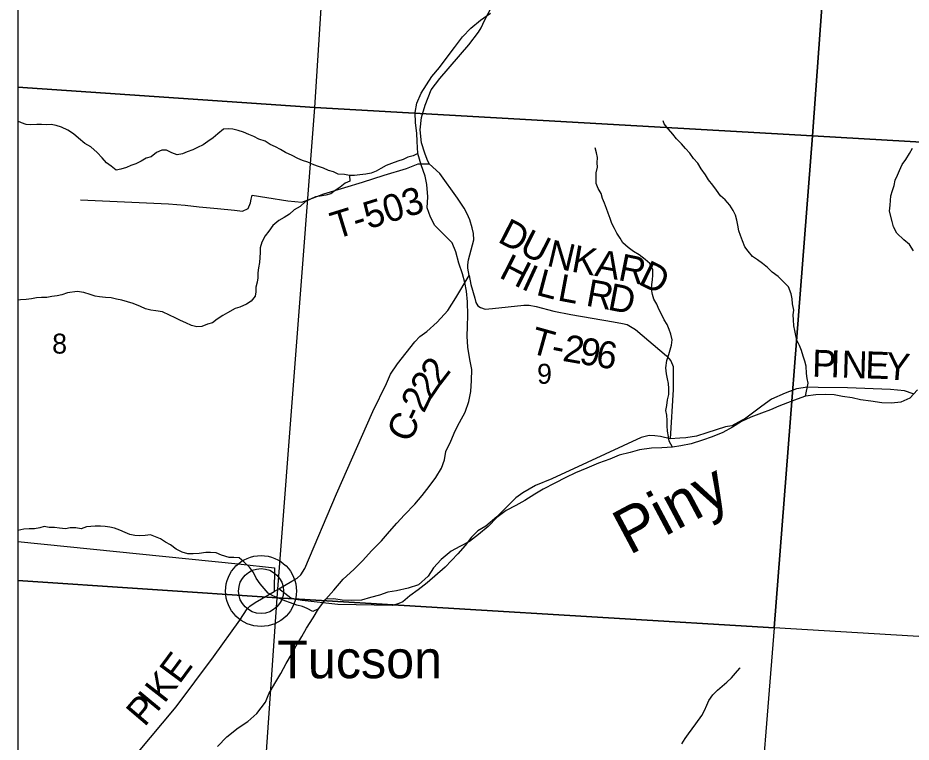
# Model space of a CAD drawing. Extents: x -13.1 to 43.1, y 0 to 22.
# Drawn here: x 2.1 to 3.976, y 14.849 to 16.37 of the extents above; entities that cross this region are included whole.
import ezdxf

# ---------------------------------------------------------------- set-up
doc = ezdxf.new("R2010")
doc.units = 0
for name, color, linetype in [('GM_X_Corporation', 7, 'Continuous'), ('GM_X_County_Road', 7, 'Continuous'), ('GM_X_County_Road_Text', 7, 'Continuous'), ('GM_X_Minor_River', 7, 'Continuous'), ('GM_X_Minor_River_Text', 7, 'Continuous'), ('GM_X_Section_Text', 7, 'Continuous'), ('GM_X_Township_Road', 7, 'Continuous'), ('GM_X_Township_Road_Text', 7, 'Continuous'), ('GM_X_Unincorporated', 7, 'Continuous'), ('GM_X_Unincorporated_Location', 7, 'Continuous'), ('GM_X_Unincorporated_Text', 7, 'Continuous'), ('SH_Data', 7, 'Continuous')]:
    doc.layers.add(name, color=color, linetype=linetype)

msp = doc.modelspace()

# ---------------------------------------------------------------- linework, layer by layer
at = {"layer": 'GM_X_Corporation'}
for points in [[(7.0807, 20.9), (2.1, 20.9), (2.1, 14.1), (6.6193, 14.1), (6.6994, 15.2069), (6.7531, 15.956), (6.8236, 16.9075), (6.9509, 19.0179), (7.0108, 19.8446), (7.0164, 19.8954), (7.0617, 20.6133)], [(7.0804, 20.9), (2.1, 20.9), (2.1, 14.1), (6.619, 14.1), (6.6992, 15.2074), (6.7528, 15.9566), (6.8234, 16.908), (6.8365, 17.1257), (6.9507, 19.0184), (6.9616, 19.1692), (7.0106, 19.8452), (7.0162, 19.896), (7.0615, 20.6138)], [(2.1, 17.2165), (2.1, 16.2245), (2.7236, 16.1815), (2.7867, 17.1698)], [(2.1, 17.2152), (2.1, 14.1), (6.619, 14.1), (6.6992, 15.2074), (6.7528, 15.9566), (6.8234, 16.908), (4.4304, 17.0575), (3.8328, 17.0966), (2.8442, 17.1637), (2.1437, 17.2135)], [(2.8499, 17.1651), (3.8395, 17.0976), (3.7693, 16.1222), (2.7236, 16.1815), (2.7867, 17.1698)], [(3.8395, 17.0976), (4.8272, 17.0344), (4.7589, 16.0643), (3.7693, 16.1222)], [(2.1, 16.2245), (2.1, 15.1883), (2.6447, 15.1518), (2.7236, 16.1815)], [(2.7236, 16.1815), (3.7693, 16.1222), (3.6885, 15.0891), (2.6447, 15.1518)], [(3.7693, 16.1222), (4.7589, 16.0643), (4.6921, 15.0289), (3.6885, 15.0891)], [(2.1, 15.1883), (2.1, 14.2382), (2.5786, 14.2031), (2.6447, 15.1518)], [(2.6447, 15.1518), (3.6885, 15.0891), (3.6113, 14.1287), (2.5786, 14.2031)], [(4.0665, 14.1), (4.6107, 14.1), (4.6921, 15.0289), (3.6885, 15.0891), (3.6113, 14.1287)]]:
    msp.add_lwpolyline(points, close=True, dxfattribs=at)
at = {"layer": 'GM_X_County_Road'}
for points in [[(3.048, 15.8288), (3.0449, 15.8441), (3.0451, 15.8513), (3.0464, 15.8615), (3.0576, 15.9035), (3.0567, 15.9169), (3.0539, 15.9291), (3.0493, 15.9455), (3.0439, 15.9582), (3.0376, 15.9701), (3.0232, 15.991), (2.9865, 16.0431), (2.964, 16.0633), (2.9597, 16.0725), (2.955, 16.0859), (2.9478, 16.1074), (2.9453, 16.1348), (2.9481, 16.1606), (2.9552, 16.1863), (2.9684, 16.2184), (2.9864, 16.2424), (3.047, 16.3134), (3.0677, 16.3396), (3.0733, 16.3486), (3.0801, 16.364), (3.1423, 16.4836)], [(2.3498, 14.8244), (2.4327, 14.9227), (2.5111, 15.028), (2.5661, 15.1052), (2.5814, 15.1284), (2.5873, 15.1344), (2.5985, 15.1418), (2.6383, 15.1648), (2.6479, 15.1704), (2.6757, 15.1869), (2.6865, 15.1932), (2.6942, 15.2003), (2.7025, 15.2134), (2.7694, 15.3702), (2.8454, 15.5428), (2.8741, 15.6019), (2.8829, 15.6212), (2.8974, 15.6429), (2.9335, 15.6897), (2.9444, 15.7009), (2.9587, 15.7112), (2.9808, 15.7309), (3.0034, 15.7552), (3.02, 15.7815), (3.048, 15.8288)], [(3.9804, 15.5805), (3.9619, 15.5866), (3.9326, 15.5891), (3.8423, 15.5925), (3.7806, 15.5938), (3.7588, 15.5939), (3.7351, 15.5906), (3.7113, 15.5815), (3.6828, 15.5692), (3.6627, 15.5544), (3.629, 15.5292), (3.5997, 15.5131), (3.5863, 15.5107), (3.5468, 15.4986), (3.5253, 15.4915), (3.5031, 15.4877), (3.4905, 15.4872), (3.4699, 15.4858), (3.4494, 15.4908), (3.4376, 15.4921), (3.4258, 15.4924), (3.4093, 15.4882), (3.2958, 15.4361), (3.2215, 15.4015), (3.1873, 15.3878), (3.1606, 15.372), (3.1459, 15.3617), (3.1058, 15.3218), (3.0829, 15.3025), (3.0663, 15.2922), (3.0531, 15.2795), (3.0394, 15.2616), (3.0238, 15.244), (2.9973, 15.216), (2.96, 15.183), (2.941, 15.1689), (2.9232, 15.156), (2.9085, 15.1437), (2.9, 15.1397), (2.887, 15.1354), (2.7719, 15.1378), (2.6973, 15.1462), (2.684, 15.1484), (2.6734, 15.1512), (2.6479, 15.1704)]]:
    msp.add_lwpolyline(points, dxfattribs=at)
at = {"layer": 'GM_X_Minor_River'}
for points in [[(2.6746, 15.0325), (2.6846, 15.0507), (2.6961, 15.0704), (2.7061, 15.0878), (2.7199, 15.1097), (2.7314, 15.1287), (2.7467, 15.1491), (2.7636, 15.168), (2.7835, 15.1907), (2.8056, 15.211), (2.824, 15.2292), (2.8431, 15.2511), (2.8638, 15.2715), (2.8806, 15.2911), (2.8959, 15.3085), (2.912, 15.3259), (2.9334, 15.3486), (2.9495, 15.3667), (2.964, 15.3856), (2.9778, 15.4045), (2.9901, 15.4242), (2.9963, 15.4416), (2.9987, 15.4591), (3.0094, 15.4811), (3.0187, 15.5023), (3.0279, 15.5197), (3.0394, 15.5416), (3.0472, 15.5644), (3.0511, 15.5849), (3.0527, 15.6084), (3.0536, 15.6312), (3.0492, 15.6524), (3.0448, 15.6783), (3.0434, 15.7011), (3.0442, 15.7215), (3.0451, 15.7451), (3.0445, 15.7732), (3.0424, 15.796), (3.0387, 15.8142), (3.0342, 15.8324), (3.026, 15.8545), (3.02, 15.8781), (3.0125, 15.8971), (2.9951, 15.9139), (2.9755, 15.9337), (2.9664, 15.9512), (2.9597, 15.971), (2.9614, 15.9937), (2.9592, 16.0196), (2.9555, 16.0371), (2.9473, 16.0614), (2.9398, 16.085), (2.9384, 16.11), (2.9378, 16.1275), (2.9349, 16.1495), (2.9342, 16.1708), (2.9381, 16.1905), (2.9474, 16.2117), (2.9581, 16.2291), (2.9696, 16.2465), (2.9857, 16.2654), (3.0018, 16.2874), (3.0171, 16.3078), (3.034, 16.3297), (3.0516, 16.3478), (3.0714, 16.3652), (3.0928, 16.3795)], [(3.7545, 15.5753), (3.7602, 15.6026), (3.7581, 15.6125), (3.7567, 15.6228), (3.7554, 15.638), (3.7528, 15.6486), (3.7495, 15.6593), (3.7459, 15.6711), (3.7415, 15.6818), (3.7363, 15.6929), (3.7341, 15.7028), (3.7316, 15.7131), (3.7298, 15.723), (3.7288, 15.7359), (3.7286, 15.7462), (3.7298, 15.756), (3.7273, 15.7693), (3.7263, 15.78), (3.7245, 15.7903), (3.7183, 15.8048), (3.7089, 15.8148), (3.6972, 15.8267), (3.6844, 15.8356), (3.6743, 15.8452), (3.6641, 15.8541), (3.6536, 15.8614), (3.6426, 15.8684), (3.6337, 15.8795), (3.6265, 15.8891), (3.6221, 15.9017), (3.6177, 15.9124), (3.614, 15.9227), (3.6123, 15.9345), (3.6101, 15.9452), (3.6072, 15.9551), (3.6024, 15.965), (3.5953, 15.9765), (3.5852, 15.9876), (3.5754, 15.9961), (3.5672, 16.0076), (3.5593, 16.0183), (3.5504, 16.0298), (3.5444, 16.0402), (3.5354, 16.0524), (3.5284, 16.0647), (3.519, 16.0747), (3.5111, 16.0854), (3.5021, 16.0954), (3.4935, 16.1054), (3.4834, 16.1154), (3.4755, 16.1257), (3.4665, 16.1361), (3.4575, 16.1469), (3.4553, 16.1537)], [(2.9398, 16.085), (2.9299, 16.0799), (2.9189, 16.0774), (2.9089, 16.0726), (2.8979, 16.0685), (2.8845, 16.0638), (2.8734, 16.0594), (2.8623, 16.0534), (2.8528, 16.0475), (2.8417, 16.0438), (2.8306, 16.0417), (2.8185, 16.0403), (2.807, 16.0389), (2.7968, 16.0387), (2.7862, 16.0411), (2.7725, 16.0417), (2.7627, 16.0463), (2.7521, 16.0495), (2.7422, 16.0538), (2.7313, 16.0574), (2.7214, 16.0609), (2.7093, 16.0664), (2.698, 16.0703), (2.6878, 16.0743), (2.676, 16.0805), (2.6624, 16.0867), (2.6515, 16.0933), (2.6413, 16.0988), (2.63, 16.1039), (2.6194, 16.1108), (2.6062, 16.1152), (2.5956, 16.1203), (2.585, 16.125), (2.5737, 16.13), (2.5627, 16.1332), (2.5513, 16.136), (2.5418, 16.1369), (2.5319, 16.1359), (2.52, 16.1262), (2.5104, 16.1179), (2.4993, 16.1101), (2.489, 16.1034), (2.4771, 16.0978), (2.4672, 16.0927), (2.4557, 16.0886), (2.4458, 16.0842), (2.4347, 16.0824), (2.4234, 16.0864), (2.4124, 16.0918), (2.4022, 16.0916), (2.3915, 16.0868), (2.3799, 16.0778), (2.3697, 16.0753), (2.3589, 16.069), (2.3478, 16.0634), (2.3375, 16.0594), (2.328, 16.0553), (2.3162, 16.0517), (2.3063, 16.0499), (2.2961, 16.058), (2.2859, 16.0654), (2.2769, 16.0757), (2.2668, 16.0872), (2.2536, 16.0992), (2.2404, 16.1062), (2.2276, 16.1174), (2.2171, 16.1259), (2.205, 16.134), (2.1914, 16.1402), (2.1805, 16.1434), (2.1702, 16.1458), (2.1596, 16.1452), (2.1497, 16.1457), (2.1398, 16.1455), (2.1273, 16.1452), (2.1174, 16.1461), (2.1076, 16.1493), (2.1, 16.1529)], [(3.4748, 15.4681), (3.468, 15.4806), (3.4662, 15.4909), (3.4641, 15.5019), (3.4638, 15.513), (3.464, 15.524), (3.463, 15.5354), (3.4612, 15.5449), (3.4628, 15.5559), (3.4645, 15.5673), (3.4669, 15.579), (3.4675, 15.5911), (3.4665, 15.6022), (3.4647, 15.6117), (3.4625, 15.6223), (3.4611, 15.6345), (3.4632, 15.6501), (3.4672, 15.6625), (3.47, 15.6728), (3.4731, 15.6826), (3.474, 15.6936), (3.4711, 15.7054), (3.4682, 15.7153), (3.4638, 15.7256), (3.4574, 15.7356), (3.4515, 15.7474), (3.4463, 15.7577), (3.4419, 15.7684), (3.4355, 15.7788), (3.4326, 15.7891), (3.4305, 15.8001), (3.4314, 15.8096), (3.4326, 15.8194), (3.4339, 15.8297), (3.4336, 15.8407), (3.427, 15.8541), (3.4172, 15.8626), (3.4048, 15.8722), (3.3931, 15.8788), (3.3818, 15.8877), (3.3709, 15.8973), (3.3653, 15.9073), (3.3578, 15.9176), (3.3534, 15.9272), (3.3478, 15.9382), (3.3441, 15.9486), (3.3397, 15.9596), (3.336, 15.9692), (3.332, 15.9806), (3.3279, 15.9905), (3.325, 16.0008), (3.3187, 16.0112), (3.3146, 16.0218), (3.3144, 16.0336), (3.3149, 16.0446), (3.3173, 16.056), (3.3167, 16.0655), (3.3172, 16.0765), (3.315, 16.0864), (3.3125, 16.0967)], [(3.9814, 15.8808), (3.9725, 15.8938), (3.9608, 15.9038), (3.9458, 15.9173), (3.9391, 15.9311), (3.9366, 15.9421), (3.9307, 15.9635), (3.9324, 15.9763), (3.9329, 15.9862), (3.9338, 15.9957), (3.937, 16.007), (3.9402, 16.018), (3.9426, 16.0286), (3.9473, 16.0396), (3.9519, 16.0494), (3.957, 16.0615), (3.9648, 16.0724), (3.9725, 16.0848), (3.9787, 16.0961)], [(2.7968, 16.0387), (2.797, 16.0269), (2.7875, 16.0229), (2.7767, 16.0143), (2.7667, 16.0072), (2.7572, 16.0001), (2.7469, 15.9972), (2.7347, 15.9951), (2.7248, 15.994), (2.7148, 15.9892), (2.7041, 15.9844), (2.6926, 15.9736), (2.6804, 15.9665), (2.6704, 15.9575), (2.6596, 15.9508), (2.6482, 15.9445), (2.6355, 15.934), (2.627, 15.9216), (2.6196, 15.9118), (2.6123, 15.8986), (2.6091, 15.8869), (2.6089, 15.877), (2.6072, 15.8558), (2.6055, 15.8448), (2.6042, 15.8346), (2.6041, 15.8239), (2.6025, 15.8145), (2.6001, 15.8042), (2.6, 15.7947), (2.5983, 15.7853), (2.5902, 15.7751), (2.5799, 15.7688), (2.5665, 15.7625), (2.5566, 15.7596), (2.5405, 15.7503), (2.5302, 15.7448), (2.5187, 15.7373), (2.5091, 15.7295), (2.4984, 15.7262), (2.4866, 15.7218), (2.4759, 15.7211), (2.4646, 15.7239), (2.4525, 15.729), (2.4415, 15.7345), (2.4305, 15.74), (2.4184, 15.7454), (2.4041, 15.7521), (2.3901, 15.7545), (2.3794, 15.7562), (2.3684, 15.7586), (2.3575, 15.7637), (2.342, 15.7699), (2.3302, 15.7735), (2.3181, 15.7771), (2.3075, 15.7791), (2.2961, 15.7819), (2.2844, 15.7828), (2.2718, 15.7841), (2.2623, 15.7854), (2.2521, 15.7886), (2.2385, 15.7933), (2.2248, 15.7954), (2.2043, 15.7926), (2.1925, 15.7882), (2.1825, 15.7857), (2.1715, 15.7843), (2.1608, 15.7825), (2.1498, 15.7823), (2.1392, 15.7817), (2.1289, 15.7799), (2.1171, 15.7785), (2.1057, 15.7775), (2.1, 15.7772)], [(3.9544, 15.5629), (3.9346, 15.5607), (3.9148, 15.5615), (3.8913, 15.5647), (3.87, 15.5678), (3.8525, 15.5717), (3.832, 15.5749), (3.8146, 15.578), (3.7955, 15.5789), (3.7758, 15.5782), (3.7545, 15.5753), (3.7369, 15.5693), (3.7164, 15.561), (3.6981, 15.5543), (3.6805, 15.5468), (3.6622, 15.5393), (3.6394, 15.5311), (3.6196, 15.522), (3.6012, 15.51), (3.5806, 15.4987), (3.5585, 15.4897), (3.538, 15.483), (3.5144, 15.4755), (3.4923, 15.4711), (3.4748, 15.4681), (3.4527, 15.4667), (3.4307, 15.466), (3.4055, 15.4624), (3.3857, 15.4572), (3.3629, 15.4512), (3.3431, 15.443), (3.3195, 15.4347), (3.2951, 15.4242), (3.2714, 15.4145), (3.2508, 15.4047), (3.228, 15.3927), (3.2036, 15.3799), (3.186, 15.3693), (3.1646, 15.3565), (3.1456, 15.346), (3.1257, 15.3355), (3.1059, 15.3204), (3.0875, 15.3015), (3.0677, 15.2849), (3.0486, 15.2698), (3.028, 15.2593), (3.0104, 15.2495), (2.989, 15.2321), (2.973, 15.2148), (2.9615, 15.1974), (2.9416, 15.1792), (2.9195, 15.1718), (2.8951, 15.1666), (2.8769, 15.1636), (2.8593, 15.1576), (2.8403, 15.1524), (2.822, 15.1472), (2.8007, 15.1465), (2.7809, 15.1466), (2.7635, 15.1498), (2.7467, 15.1491)], [(3.9895, 15.5885), (3.9734, 15.5711), (3.9544, 15.5629)], [(2.7314, 15.1287), (2.7198, 15.1233), (2.7078, 15.1292), (2.6975, 15.1339), (2.6862, 15.1367), (2.6726, 15.141), (2.6604, 15.1457), (2.6483, 15.1508), (2.6366, 15.1552), (2.6257, 15.1617), (2.6174, 15.1713), (2.6088, 15.1813), (2.6002, 15.1932), (2.5947, 15.2051), (2.5864, 15.2162), (2.5744, 15.2273), (2.5646, 15.2358), (2.5536, 15.2367), (2.5437, 15.2365), (2.5278, 15.2416), (2.5165, 15.2463), (2.5043, 15.2472), (2.4948, 15.247), (2.4807, 15.2452), (2.4682, 15.2443), (2.4572, 15.244), (2.445, 15.2476), (2.4326, 15.2538), (2.4209, 15.2631), (2.4103, 15.2689), (2.3998, 15.2755), (2.3786, 15.2841), (2.3672, 15.2828), (2.3558, 15.2818), (2.3459, 15.2827), (2.3353, 15.2851), (2.3251, 15.289), (2.3141, 15.2937), (2.3031, 15.298), (2.2933, 15.3004), (2.2834, 15.3017), (2.2739, 15.3022), (2.2621, 15.302), (2.2443, 15.3007), (2.2328, 15.2966), (2.2218, 15.2991), (2.21, 15.2985), (2.1997, 15.2967), (2.1876, 15.298), (2.1766, 15.2996), (2.166, 15.2998), (2.1553, 15.3018), (2.1458, 15.2989), (2.1348, 15.2968), (2.1237, 15.2965), (2.1123, 15.2959), (2.1, 15.2933)], [(2.5191, 14.8397), (2.539, 14.8601), (2.5627, 14.879), (2.5833, 14.8918), (2.6017, 14.9092), (2.6201, 14.9326), (2.627, 14.95), (2.64, 14.972), (2.6523, 14.9932), (2.6638, 15.0136), (2.6746, 15.0325)], [(3.4945, 14.8453), (3.5014, 14.8563), (3.5084, 14.8664), (3.5165, 14.8766), (3.5242, 14.8871), (3.5366, 14.9048), (3.5421, 14.9154), (3.5468, 14.9267), (3.5514, 14.9365), (3.5599, 14.9478), (3.5692, 14.9576), (3.5792, 14.9665), (3.5888, 14.9748), (3.5991, 14.9841), (3.6072, 14.9939), (3.6165, 15.004), (3.6173, 15.0048)]]:
    msp.add_lwpolyline(points, dxfattribs=at)
at = {"layer": 'GM_X_Township_Road'}
msp.add_line((2.1, 15.2698), (2.5625, 15.2229), dxfattribs=at)
for points in [[(2.7097, 15.9878), (2.7424, 15.9999), (2.7866, 16.0137), (2.8236, 16.0248), (2.869, 16.0394), (2.9163, 16.0536), (2.9407, 16.0633), (2.964, 16.0633)], [(2.2313, 15.9877), (2.4163, 15.979), (2.4513, 15.9765), (2.481, 15.9729), (2.5195, 15.9696), (2.5552, 15.966), (2.5716, 15.9636), (2.5834, 15.9692), (2.5884, 15.981), (2.5903, 15.9887)], [(2.5903, 15.9887), (2.5923, 15.9973), (2.6232, 15.9926), (2.6673, 15.9855), (2.6966, 15.983), (2.7097, 15.9878)], [(3.048, 15.8288), (3.0513, 15.8098), (3.0595, 15.7809), (3.0622, 15.7721), (3.0659, 15.7652), (3.0716, 15.7618), (3.0815, 15.7583), (3.0971, 15.7597), (3.163, 15.7666), (3.1737, 15.7665), (3.1889, 15.7637), (3.2254, 15.7536), (3.2612, 15.7466), (3.3513, 15.7312), (3.3696, 15.7281), (3.3799, 15.7257), (3.397, 15.7154), (3.4622, 15.6602), (3.4716, 15.6495), (3.4765, 15.6377), (3.4762, 15.5894), (3.4699, 15.4858)], [(2.5625, 15.2229), (2.6393, 15.2151), (2.6383, 15.1648)]]:
    msp.add_lwpolyline(points, dxfattribs=at)
at = {"layer": 'GM_X_Unincorporated'}
for radius in [0.0744, 0.0472]:
    msp.add_circle((2.6107, 15.1661), radius, dxfattribs=at)
at = {"layer": 'GM_X_Unincorporated_Location'}
msp.add_line((2.6107, 15.1661), (2.6107, 15.1661), dxfattribs=at)
at = {"layer": 'SH_Data'}
msp.add_line((2.1, 20.9), (2.1, 14.1), dxfattribs=at)

# ---------------------------------------------------------------- texts
at = {"layer": 'GM_X_County_Road_Text'}
for s, rotation, p in [('P', 358.2703, (3.7675, 15.6162)), ('I', 358.2667, (3.8058, 15.615)), ('N', 358.2658, (3.8291, 15.6143)), ('E', 358.114, (3.8791, 15.6128)), ('Y', 355.2079, (3.9208, 15.6114)), ('2', 52.468, (2.9859, 15.5952)), ('2', 55.8631, (2.9669, 15.5671)), ('2', 63.988, (2.9527, 15.5378)), ('C', 65.4529, (2.9238, 15.4751)), ('-', 64.65, (2.9429, 15.517)), ('E', 53.4079, (2.4392, 14.969)), ('K', 52.0152, (2.4075, 14.9284)), ('I', 50.3237, (2.3915, 14.909)), ('P', 49.4966, (2.366, 14.8792))]:
    msp.add_text(s, height=0.0568, rotation=rotation, dxfattribs=at).set_placement(p)
at = {"layer": 'GM_X_Minor_River_Text'}
msp.add_text('Piny', height=0.0947, rotation=28.0029, dxfattribs=at).set_placement((3.3843, 15.2406))
at = {"layer": 'GM_X_Section_Text'}
for s, p in [('8', (2.1721, 15.6647)), ('9', (3.1905, 15.6014))]:
    msp.add_text(s, height=0.0419, rotation=0, dxfattribs=at).set_placement(p)
at = {"layer": 'GM_X_Township_Road_Text'}
for s, height, rotation, p in [('T-503', 0.05682, 17.1628, (2.7675, 15.9045)), ('D', 0.0568, 332.8517, (3.1056, 15.9001)), ('U', 0.0568, 333.0685, (3.1503, 15.8772)), ('N', 0.0568, 346.6326, (3.2087, 15.8495)), ('K', 0.0568, 349.7717, (3.2606, 15.8372)), ('H', 0.0568, 333.0603, (3.1085, 15.8255)), ('A', 0.0568, 349.6932, (3.3098, 15.8284)), ('R', 0.0568, 348.6304, (3.3587, 15.8195)), ('D', 0.0568, 333.7119, (3.4008, 15.8115)), ('I', 0.0568, 335.1781, (3.1551, 15.8019)), ('L', 0.0568, 345.2561, (3.1863, 15.7885)), ('L', 0.0568, 349.4043, (3.2317, 15.7767)), ('R', 0.0568, 349.6749, (3.291, 15.7657)), ('D', 0.0568, 349.123, (3.3368, 15.7573)), ('T', 0.0568, 344.4626, (3.1725, 15.667)), ('2', 0.0568, 350.0719, (3.2422, 15.6497)), ('9', 0.0568, 350.4141, (3.2771, 15.6437)), ('6', 0.0568, 350.6312, (3.3118, 15.6378)), ('-', 0.0568, 348.7611, (3.2179, 15.6546))]:
    msp.add_text(s, height=height, rotation=rotation, dxfattribs=at).set_placement(p)
at = {"layer": 'GM_X_Unincorporated_Text'}
msp.add_text('Tucson', height=0.07898, rotation=0, dxfattribs=at).set_placement((2.6446, 14.983))

doc.saveas('drawing.dxf')
